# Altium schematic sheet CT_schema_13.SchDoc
size 564 x 458 mm
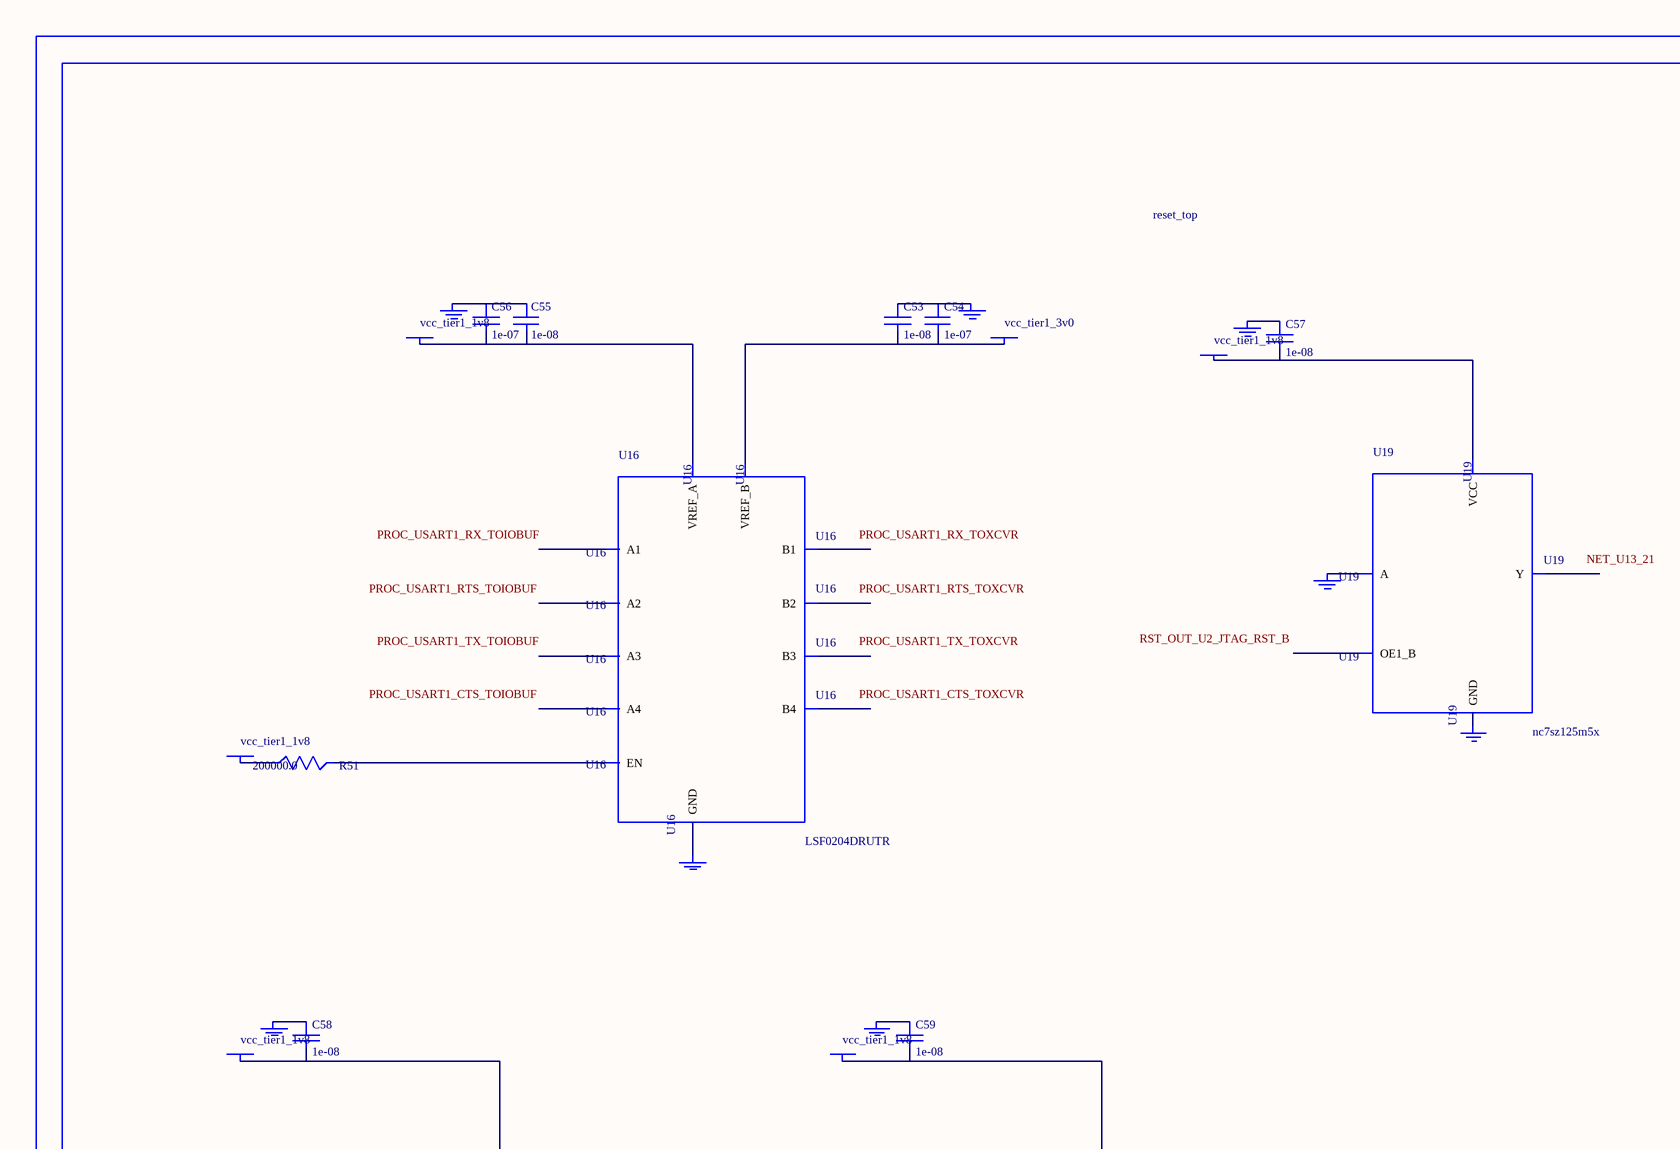
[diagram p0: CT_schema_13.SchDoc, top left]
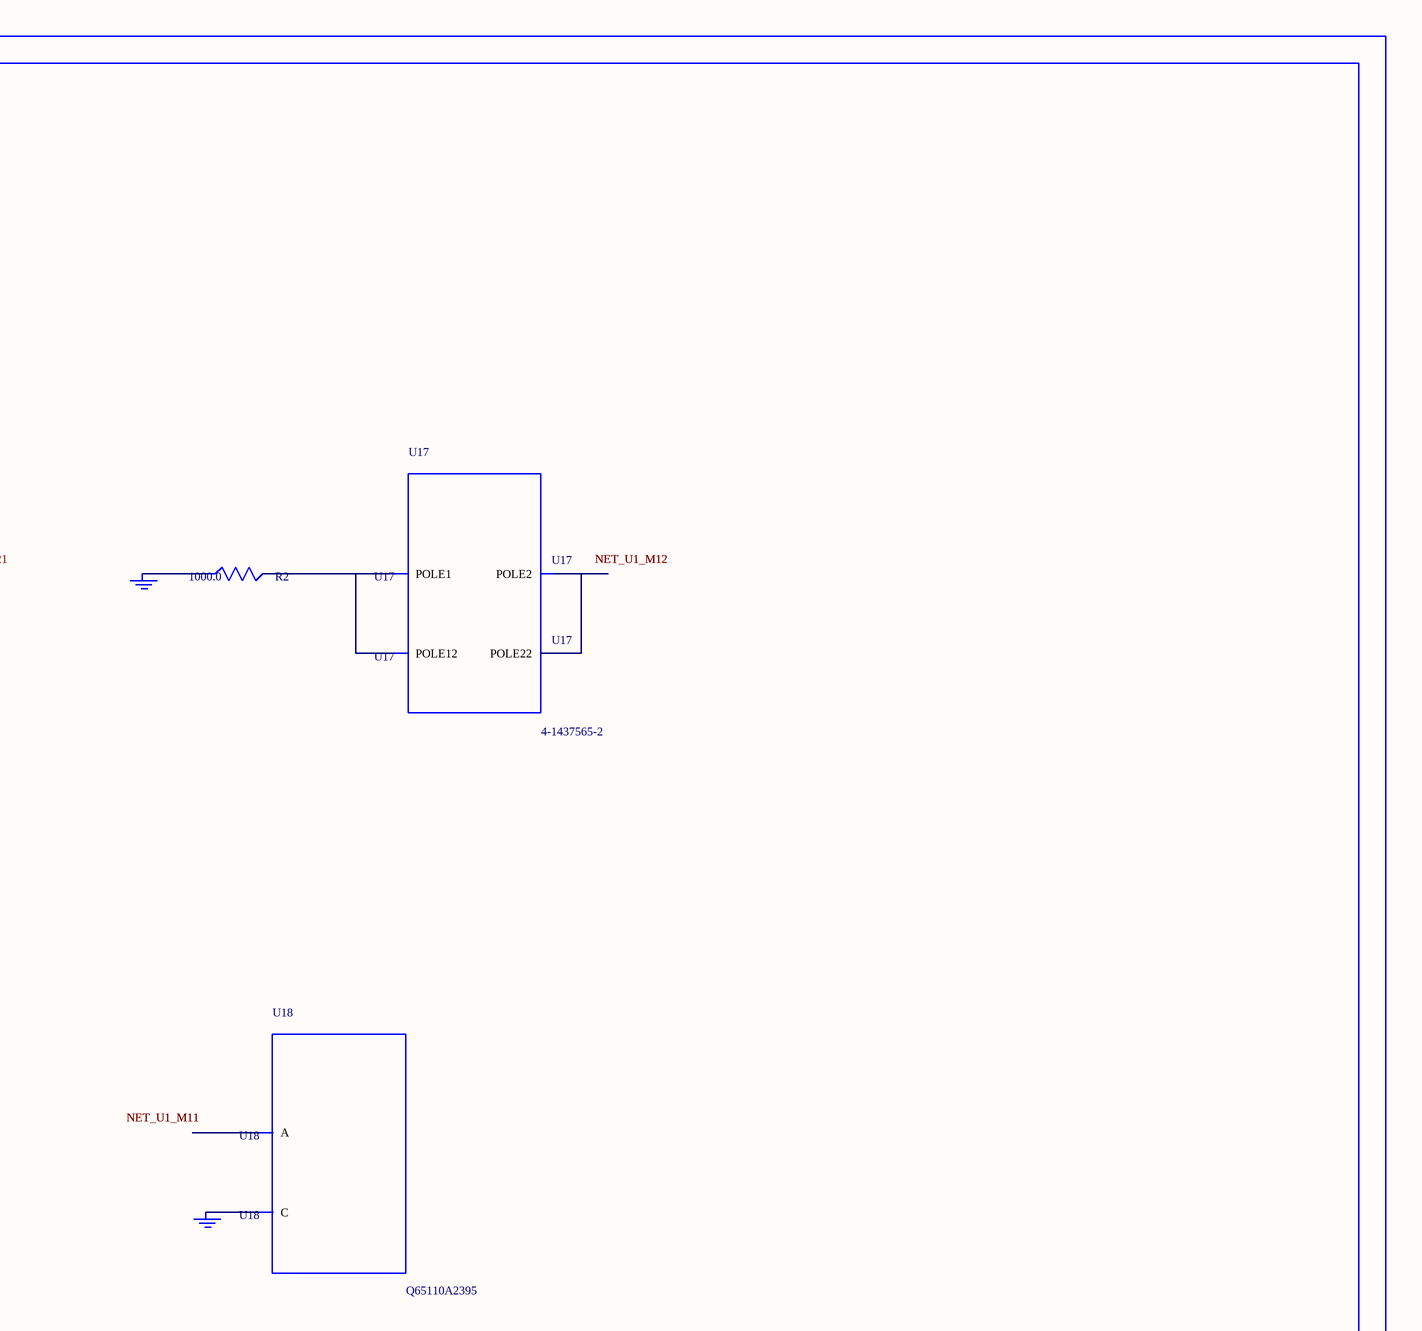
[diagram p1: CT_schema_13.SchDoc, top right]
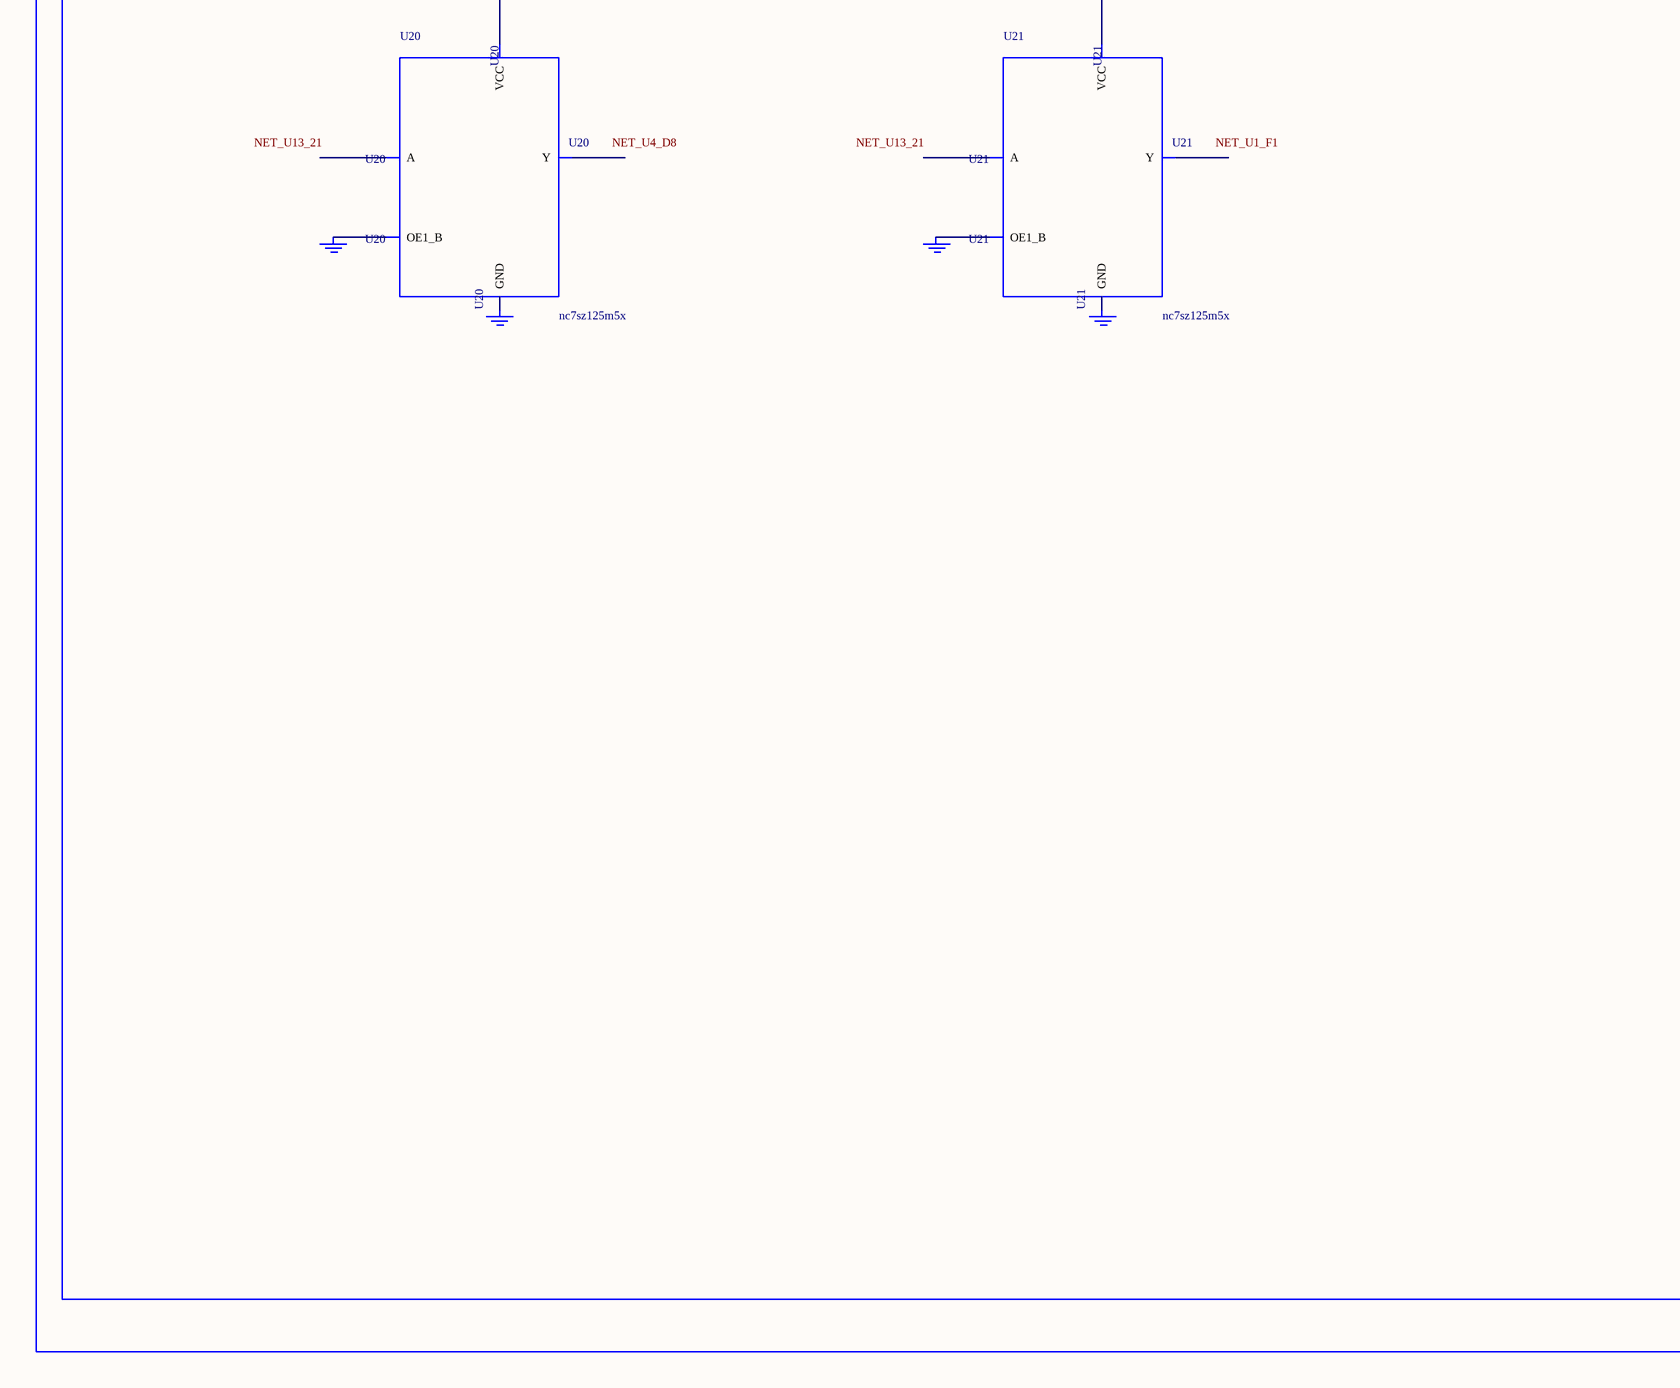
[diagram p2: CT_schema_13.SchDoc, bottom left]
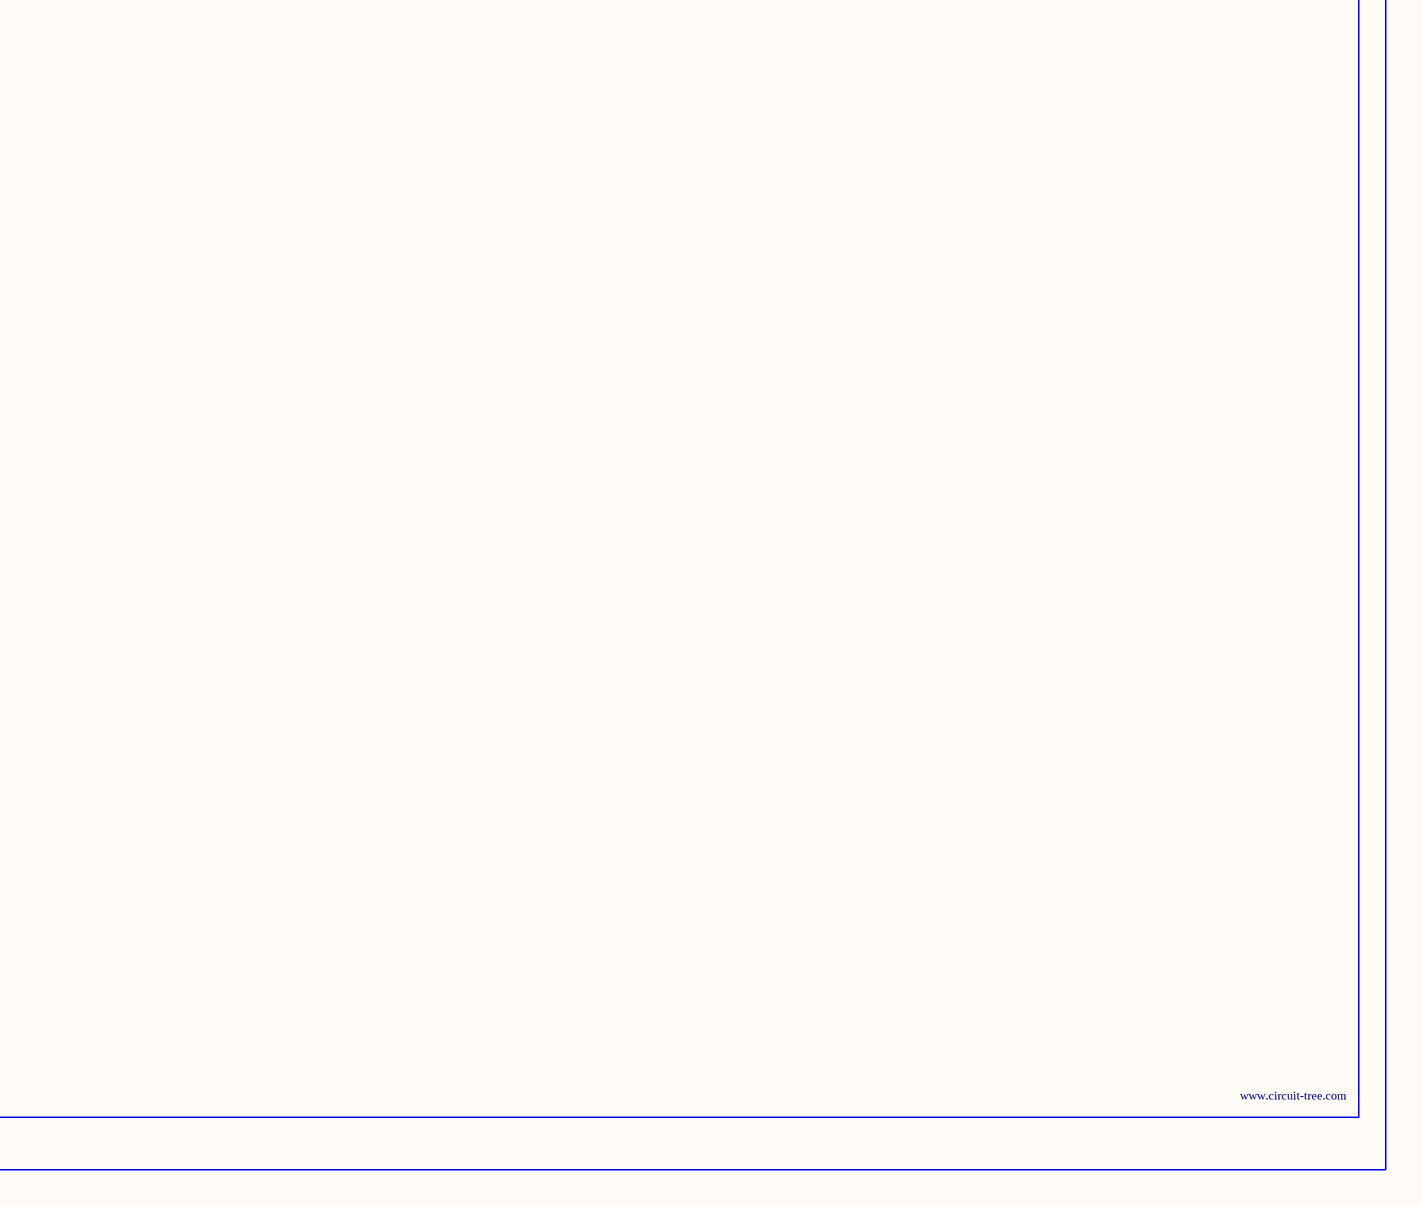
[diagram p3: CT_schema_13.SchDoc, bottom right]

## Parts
BORDER12  (no value)
C53  1e-08  [C0402]
C54  1e-07  [C0402]
C55  1e-08  [C0402]
C56  1e-07  [C0402]
C57  1e-08  [C0402]
C58  1e-08  [C0402]
C59  1e-08  [C0402]
GND_INSTANCE_12_0  (no value)
GND_INSTANCE_12_1  (no value)
GND_INSTANCE_12_2  (no value)
GND_INSTANCE_12_3  (no value)
GND_INSTANCE_12_4  (no value)
GND_INSTANCE_12_5  (no value)
GND_INSTANCE_12_6  (no value)
GND_INSTANCE_12_7  (no value)
GND_INSTANCE_12_8  (no value)
GND_INSTANCE_12_9  (no value)
GND_INSTANCE_12_10  (no value)
GND_INSTANCE_12_11  (no value)
GND_INSTANCE_12_12  (no value)
GND_INSTANCE_12_13  (no value)
POWER_INSTANCE_12_0  vcc_tier1_1v8
POWER_INSTANCE_12_1  vcc_tier1_3v0
POWER_INSTANCE_12_2  vcc_tier1_1v8
POWER_INSTANCE_12_3  vcc_tier1_1v8
POWER_INSTANCE_12_4  vcc_tier1_1v8
POWER_INSTANCE_12_5  vcc_tier1_1v8
R2  1000.0  [R0603]
R51  200000.0  [R0603]
U16  LSF0204DRUTR  [RUT0012A]
U17  4-1437565-2  [SW_4-1437565-2]
U18  Q65110A2395  [LGM67K-G1J2-24-Z]
U19  nc7sz125m5x  [NC7SZ125M5X]
U20  nc7sz125m5x  [NC7SZ125M5X]
U21  nc7sz125m5x  [NC7SZ125M5X]

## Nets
NetC53_1: C53.1 C54.1 GND_INSTANCE_12_1.0(GND)
NetC53_2: C53.2 C54.2 POWER_INSTANCE_12_1.0(PWR) U16.11(VREF_B)
NetC55_1: C55.1 C56.1 GND_INSTANCE_12_0.0(GND)
NetC55_2: C55.2 C56.2 POWER_INSTANCE_12_0.0(PWR) U16.1(VREF_A)
NetC57_1: C57.1 GND_INSTANCE_12_5.0(GND)
NetC57_2: C57.2 POWER_INSTANCE_12_3.0(PWR) U19.5(VCC)
NetC58_1: C58.1 GND_INSTANCE_12_8.0(GND)
NetC58_2: C58.2 POWER_INSTANCE_12_4.0(PWR) U20.5(VCC)
NetC59_1: C59.1 GND_INSTANCE_12_11.0(GND)
NetC59_2: C59.2 POWER_INSTANCE_12_5.0(PWR) U21.5(VCC)
NetGND_INSTANCE_12_2_0: GND_INSTANCE_12_2.0(GND) U16.6(GND)
NetGND_INSTANCE_12_3_0: GND_INSTANCE_12_3.0(GND) R2.1
NetGND_INSTANCE_12_4_0: GND_INSTANCE_12_4.0(GND) U18.C
NetGND_INSTANCE_12_6_0: GND_INSTANCE_12_6.0(GND) U19.2(A)
NetGND_INSTANCE_12_7_0: GND_INSTANCE_12_7.0(GND) U19.3(GND)
NetGND_INSTANCE_12_9_0: GND_INSTANCE_12_9.0(GND) U20.1(OE1_B)
NetGND_INSTANCE_12_10_0: GND_INSTANCE_12_10.0(GND) U20.3(GND)
NetGND_INSTANCE_12_12_0: GND_INSTANCE_12_12.0(GND) U21.1(OE1_B)
NetGND_INSTANCE_12_13_0: GND_INSTANCE_12_13.0(GND) U21.3(GND)
NetPOWER_INSTANCE_12_2_0: POWER_INSTANCE_12_2.0(PWR) R51.1
NetR2_2: R2.2 U17.1(POLE1) U17.2(POLE12)
NetR51_2: R51.2 U16.12(EN)
NetU17_3: U17.3(POLE2) U17.4(POLE22)

Not connected (* = marked no-connect by the designer): U16 2(A1) 3(A2) 4(A3) 5(A4) 7(B4) 8(B3) 9(B2) 10(B1); U18 A; U19 1(OE1_B) 4(Y); U20 2(A) 4(Y); U21 2(A) 4(Y)

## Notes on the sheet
- Labels drawn without touching a wire or pin: NET_U1_F1, NET_U4_D8, NET_U13_21, PROC_USART1_CTS_TOIOBUF, PROC_USART1_CTS_TOXCVR, PROC_USART1_RTS_TOIOBUF, PROC_USART1_RTS_TOXCVR, PROC_USART1_RX_TOIOBUF, PROC_USART1_RX_TOXCVR, PROC_USART1_TX_TOIOBUF, PROC_USART1_TX_TOXCVR, RST_OUT_U2_JTAG_RST_B

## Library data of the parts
BORDER12 = BORDER_PAGE12
C53 C55 C57-C59 = C0402C103K3RAC
C54 C56 = C0402C104K3RACTU
GND_INSTANCE_12_0-GND_INSTANCE_12_13 = GND
POWER_INSTANCE_12_0-POWER_INSTANCE_12_5 = PWR
R2 = RC0603JR-071KL
R51 = RC0603JR-07200KL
